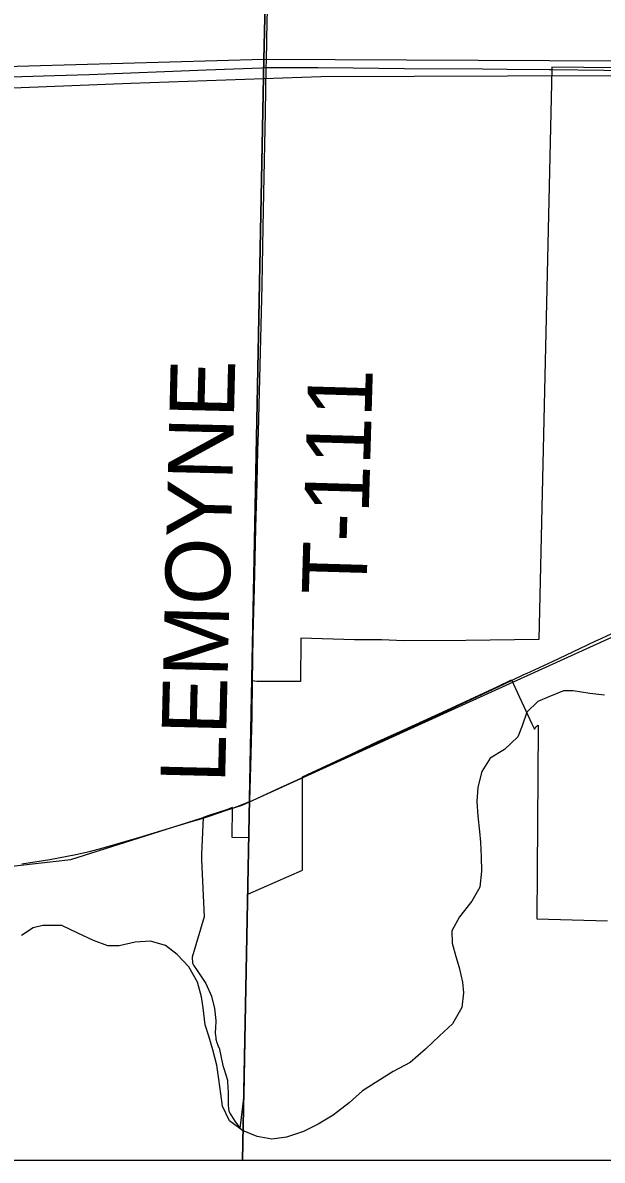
# Model space of a CAD drawing. Extents: x 0 to 34, y 0 to 22.
# Drawn here: x 4.218 to 4.727, y 14.1 to 15.1 of the extents above; entities that cross this region are included whole.
import ezdxf

# ---------------------------------------------------------------- set-up
doc = ezdxf.new("R2010")
doc.units = 0
for name, color, linetype in [('GM_X_City_Street', 7, 'Continuous'), ('GM_X_Major_River', 7, 'Continuous'), ('GM_X_Minor_River', 7, 'Continuous'), ('GM_X_Rail_Line', 7, 'Continuous'), ('GM_X_Section', 7, 'Continuous'), ('GM_X_State_Route', 7, 'Continuous'), ('GM_X_Township_Road', 7, 'Continuous'), ('GM_X_Township_Road_Text', 7, 'Continuous'), ('GM_X_US_Route', 7, 'Continuous'), ('SH_Cut_Line', 7, 'Continuous'), ('SH_Data', 7, 'Continuous')]:
    doc.layers.add(name, color=color, linetype=linetype)

msp = doc.modelspace()

# ---------------------------------------------------------------- linework, layer by layer
at = {"layer": 'GM_X_City_Street'}
for points in [[(3.40925, 14.1), (4.4112, 14.1), (4.42986, 15.0671), (3.43781, 15.03908)], [(4.4112, 14.1), (5.41501, 14.1), (5.43209, 15.05104), (4.99489, 15.06466), (4.42986, 15.0671)]]:
    msp.add_lwpolyline(points, close=True, dxfattribs=at)
at = {"layer": 'GM_X_Major_River'}
for points in [[(4.72936, 14.50854), (4.71652, 14.50998), (4.70175, 14.51246), (4.69348, 14.51244), (4.68047, 14.50706), (4.67091, 14.50312), (4.66121, 14.49387), (4.65712, 14.48182), (4.65309, 14.47205), (4.64146, 14.46095), (4.62877, 14.45328), (4.62167, 14.44169), (4.61791, 14.42774), (4.61723, 14.41523), (4.61804, 14.40231), (4.6196, 14.38899), (4.62051, 14.37948), (4.62094, 14.36656), (4.62139, 14.35403), (4.61991, 14.34002), (4.61278, 14.32767), (4.60184, 14.31389), (4.59509, 14.30153), (4.59559, 14.29089), (4.5987, 14.27905), (4.6015, 14.2695), (4.60458, 14.25652), (4.60548, 14.24701), (4.60403, 14.23414), (4.59572, 14.21992), (4.58447, 14.20919), (4.57207, 14.19772), (4.55852, 14.1859), (4.54356, 14.17791), (4.51663, 14.16111), (4.50501, 14.15038), (4.49073, 14.13972), (4.47766, 14.13169), (4.46462, 14.12517), (4.44973, 14.12022), (4.43681, 14.11863), (4.42399, 14.12084), (4.41124, 14.12609), (4.39972, 14.13471), (4.39359, 14.14739), (4.39198, 14.15843), (4.3904, 14.17137)], [(4.3904, 14.17137), (4.38843, 14.18357), (4.38498, 14.19693), (4.38149, 14.20916), (4.37833, 14.21911), (4.37643, 14.23395), (4.37515, 14.24347), (4.37168, 14.25646), (4.36406, 14.26993), (4.35373, 14.2808), (4.34332, 14.28865), (4.33016, 14.29238), (4.31688, 14.29156), (4.3028, 14.28849), (4.29257, 14.28836), (4.28019, 14.29321), (4.26634, 14.29962), (4.25212, 14.30641), (4.2355, 14.3064), (4.22707, 14.30436), (4.21668, 14.2974)]]:
    msp.add_lwpolyline(points, dxfattribs=at)
at = {"layer": 'GM_X_Minor_River'}
msp.add_lwpolyline([(3.45163, 15.02751), (3.60349, 15.02764), (3.81332, 15.02901), (4.03843, 15.03571), (4.31288, 15.04653), (4.48003, 15.05235), (4.64402, 15.05294), (4.8186, 15.05326)], dxfattribs=at)
at = {"layer": 'GM_X_Rail_Line'}
msp.add_lwpolyline([(2.68691, 14.60752), (3.08114, 14.50951), (3.112, 14.50256), (3.139, 14.50488), (3.20587, 14.51042), (3.29408, 14.49955), (3.64881, 14.37466), (3.8233, 14.33288), (3.89041, 14.32244), (4.14097, 14.35079), (4.26028, 14.36421), (4.41091, 14.41195), (4.90666, 14.63728)], dxfattribs=at)
at = {"layer": 'GM_X_Section'}
for points in [[(3.47539, 16.03654), (4.45315, 16.03743), (4.42986, 15.0671), (3.43781, 15.03908), (3.46857, 16.03661)], [(4.47855, 16.03754), (5.45704, 16.03462), (5.43209, 15.05104), (4.99489, 15.06466), (4.42986, 15.0671), (4.45315, 16.03743)]]:
    msp.add_lwpolyline(points, close=True, dxfattribs=at)
at = {"layer": 'GM_X_State_Route'}
msp.add_line((4.64774, 14.52146), (4.65919, 14.52699), dxfattribs=at)
for points in [[(4.72277, 14.55671), (4.73541, 14.56257), (4.7467, 14.56765), (4.76643, 14.57668), (4.78481, 14.58467), (4.78666, 14.58548), (4.79647, 14.58979), (4.81699, 14.59893), (4.83251, 14.60583), (4.84081, 14.60987), (4.84786, 14.61297), (4.85108, 14.61449), (4.85952, 14.6184), (4.86452, 14.62049), (4.87303, 14.62409), (4.88145, 14.62785), (4.89545, 14.63431), (4.89952, 14.63616), (4.91379, 14.64262), (4.91575, 14.64353)], [(4.65919, 14.52699), (4.66095, 14.52784), (4.68362, 14.53828), (4.70769, 14.54966), (4.72187, 14.5563), (4.72277, 14.55671)], [(4.46398, 14.43644), (4.48114, 14.44436), (4.50646, 14.45603), (4.5303, 14.46727), (4.55011, 14.47611), (4.59088, 14.49502), (4.63588, 14.51586), (4.64774, 14.52146)], [(4.41737, 14.41528), (4.41995, 14.41625), (4.44463, 14.42742), (4.45938, 14.43422), (4.46398, 14.43644)], [(4.4027, 14.40949), (4.41164, 14.41299), (4.41737, 14.41528)], [(4.37568, 14.40035), (4.37663, 14.40062), (4.38167, 14.40232), (4.39716, 14.40748), (4.4027, 14.40949)], [(4.2172, 14.36045), (4.24173, 14.36438), (4.24938, 14.36569), (4.26463, 14.36857), (4.27673, 14.37127), (4.28873, 14.37442), (4.32006, 14.38352), (4.34682, 14.3917), (4.36617, 14.39758), (4.37568, 14.40035)]]:
    msp.add_lwpolyline(points, dxfattribs=at)
at = {"layer": 'GM_X_Township_Road'}
for points in [[(4.43205, 15.06018), (4.43215, 15.06598), (4.43293, 15.1008), (4.43418, 15.14678), (4.43526, 15.20023), (4.43597, 15.23442), (4.43697, 15.28165), (4.43757, 15.32766), (4.43829, 15.35812), (4.43897, 15.3836), (4.44019, 15.44079), (4.44101, 15.4762), (4.44306, 15.57504), (4.4438, 15.60426), (4.44503, 15.63967), (4.44628, 15.69934), (4.44727, 15.75154), (4.44834, 15.81744), (4.44999, 15.89886), (4.45055, 15.92808), (4.4518, 15.98028), (4.45229, 16.01509), (4.45243, 16.02534)], [(3.43961, 15.03511), (3.46122, 15.03546), (3.51871, 15.03639), (3.56593, 15.03731), (3.60425, 15.03806), (3.64628, 15.0389), (3.73076, 15.04009), (3.78134, 15.04077), (3.81235, 15.04127), (3.86006, 15.04211), (3.9127, 15.04328), (3.93565, 15.04403), (3.99338, 15.0457), (4.04191, 15.04737), (4.0888, 15.04845), (4.15368, 15.05029), (4.19795, 15.05162), (4.24582, 15.05328), (4.27625, 15.05412), (4.37906, 15.05818), (4.42775, 15.06002), (4.43205, 15.06018)], [(4.76758, 15.05968), (4.68321, 15.06037), (4.68318, 15.05904), (4.67175, 14.55764), (4.60758, 14.5566), (4.55313, 14.55627), (4.53327, 14.5573), (4.50957, 14.55733), (4.46251, 14.55861), (4.46224, 14.52071), (4.42382, 14.52059), (4.41957, 14.52112), (4.41938, 14.49103), (4.41823, 14.44631), (4.41714, 14.41583), (4.41652, 14.38322), (4.40214, 14.38361), (4.40247, 14.41005), (4.39694, 14.40803), (4.38144, 14.40288), (4.37641, 14.40118), (4.375, 14.36853), (4.37515, 14.36402), (4.37728, 14.314), (4.36685, 14.27841), (4.36727, 14.27318), (4.36804, 14.27151), (4.37118, 14.26661), (4.37887, 14.25543), (4.3838, 14.24423), (4.38659, 14.23328), (4.3876, 14.22281), (4.38738, 14.21586), (4.38732, 14.21522), (4.3872, 14.21327), (4.3872, 14.21135), (4.38727, 14.20982), (4.38755, 14.20759), (4.38777, 14.20641), (4.38793, 14.20566), (4.38834, 14.20417), (4.38856, 14.20343), (4.38931, 14.20123), (4.3901, 14.19946), (4.39053, 14.19864), (4.39396, 14.1834), (4.39509, 14.1796), (4.39783, 14.17041), (4.3979, 14.16897), (4.3984, 14.1594), (4.39862, 14.14819), (4.39871, 14.14572), (4.39922, 14.14313), (4.3999, 14.14128), (4.40447, 14.13425), (4.40902, 14.12797), (4.41196, 14.15228), (4.41252, 14.15733), (4.41573, 14.33371), (4.46382, 14.35476), (4.46375, 14.43699), (4.48091, 14.44491), (4.50623, 14.45658), (4.53008, 14.46782), (4.54989, 14.47666), (4.59066, 14.49558), (4.63565, 14.51641), (4.64751, 14.52202), (4.6655, 14.48334), (4.6679, 14.47893), (4.66821, 14.47934), (4.66856, 14.47971), (4.66946, 14.48097), (4.67017, 14.48161), (4.67043, 14.48191), (4.671, 14.48219), (4.67097, 14.48011), (4.67005, 14.31205), (4.73193, 14.31027)], [(4.4198, 14.52056), (4.42014, 14.53957), (4.42049, 14.56071), (4.42163, 14.60296), (4.42227, 14.62843), (4.42291, 14.65577), (4.42392, 14.69494), (4.42469, 14.72352), (4.42521, 14.73968), (4.4283, 14.86895), (4.4293, 14.91991), (4.42981, 14.94975), (4.43136, 15.0206), (4.43205, 15.06018)], [(4.43205, 15.06018), (4.45078, 15.06032), (4.47724, 15.06005), (4.5084, 15.05987), (4.55355, 15.0594), (4.62207, 15.05888), (4.64387, 15.05867), (4.68096, 15.05848), (4.68341, 15.05848)], [(4.68341, 15.05848), (4.72889, 15.05784), (4.75206, 15.05762), (4.76697, 15.05749), (4.77302, 15.05746), (4.78582, 15.05732)], [(4.41737, 14.41528), (4.41845, 14.44576), (4.4196, 14.49048), (4.4198, 14.52056)]]:
    msp.add_lwpolyline(points, dxfattribs=at)
at = {"layer": 'GM_X_US_Route'}
msp.add_lwpolyline([(3.40839, 14.1), (7.42441, 14.1)], dxfattribs=at)
at = {"layer": 'SH_Cut_Line'}
msp.add_lwpolyline([(2.1, 20.9), (2.1, 14.1), (7.42441, 14.1)], dxfattribs=at)
at = {"layer": 'SH_Data'}
msp.add_line((2.1, 14.1), (8.9, 14.1), dxfattribs=at)

# ---------------------------------------------------------------- texts
at = {"layer": 'GM_X_Township_Road_Text'}
for s, rotation, p in [('LEMOYNE', 88.60291, (4.39575, 14.43117)), ('T-111', 88.33115, (4.52001, 14.59637))]:
    msp.add_text(s, height=0.056818, rotation=rotation, dxfattribs=at).set_placement(p)

doc.saveas('drawing.dxf')
